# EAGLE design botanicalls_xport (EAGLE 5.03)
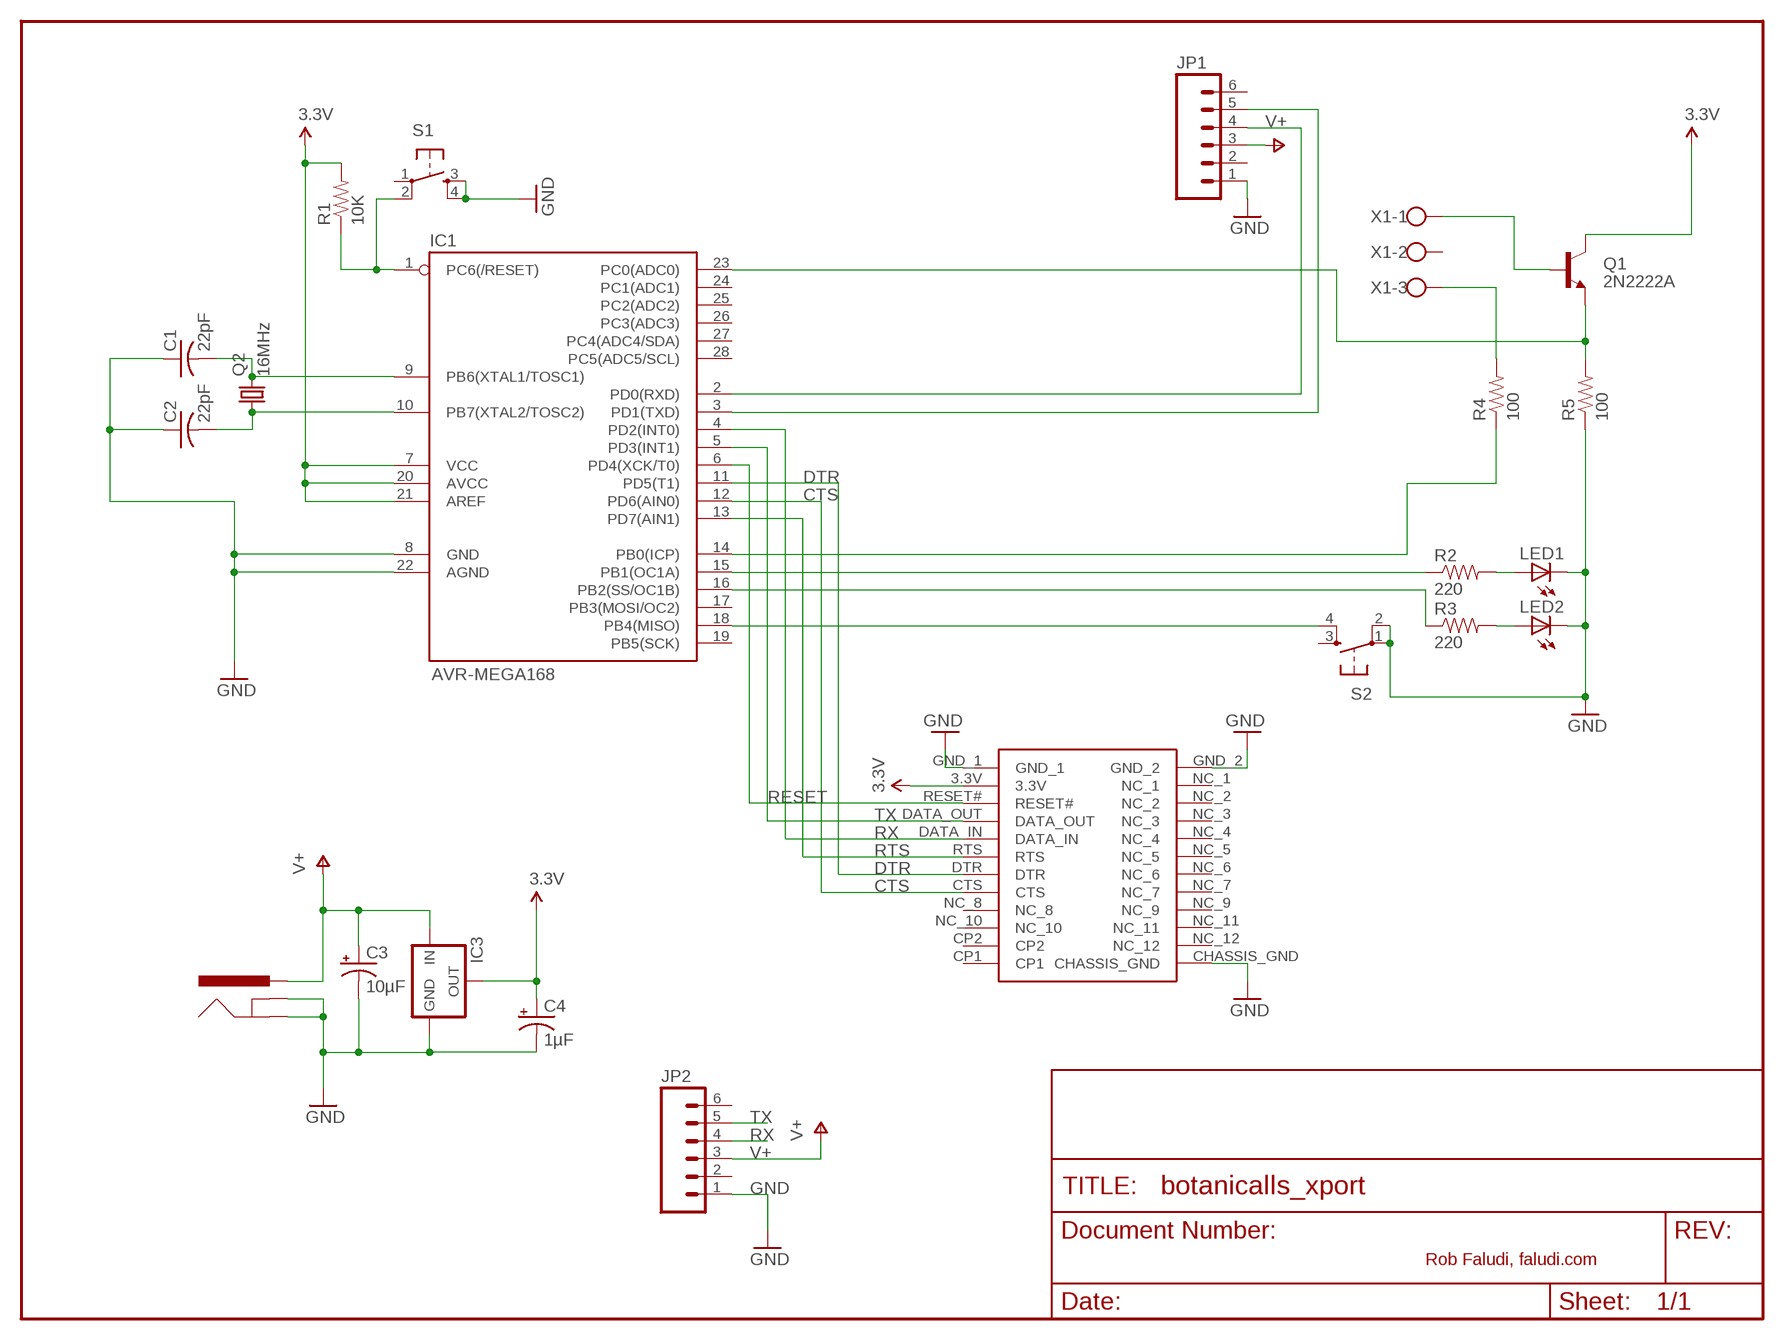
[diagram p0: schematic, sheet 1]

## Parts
C1  22pF  C-US025-025X050  [C025-025X050]
C2  22pF  C-US025-025X050  [C025-025X050]
C3  10µF  CPOL-USE2.5-5  [E2,5-5]
C4  1µF  CPOL-USE2.5-5  [E2,5-5]
IC1  AVR-MEGA168  AVR-MEGA8-P  [DIL28-3]
IC3  LD1117  [LD1117]
J1  POWER_JACKPTH  [POWER_JACK_PTH]
JP1  M06SIP  [1X06]
JP2  M06SIP  [1X06]
LED1  LED3MM  [LED3MM]
LED2  LED3MM  [LED3MM]
Q1  2N2222A  TRANSISTOR_NPNTO92  [TO-92]
Q2  16MHz  CRYTALHC49U-V  [HC49U-V]
R1  10K  RESISTORPTH1  [AXIAL-0.3]
R2  220  RESISTORPTH1  [AXIAL-0.3]
R3  220  RESISTORPTH1  [AXIAL-0.3]
R4  100  RESISTORPTH1  [AXIAL-0.3]
R5  100  RESISTORPTH1  [AXIAL-0.3]
S1  TAC_SWITCHPTH  [TACTILE-PTH]
S2  TAC_SWITCHPTH  [TACTILE-PTH]
U$3  LANTRONIX-XPORT-DIRECT  [XPORT-DIRECT-2MM]
X1  W237-03P  [W237-133]

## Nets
3.3V: C4.+ IC1.7(VCC) IC1.20(AVCC) IC1.21(AREF) IC3.GND Q1.3(C) R1.P$2 U$3.3.3V
CTS: IC1.12(PD6(AIN0)) U$3.CTS
DTR: IC1.11(PD5(T1)) U$3.DTR
GND: C1.1 C2.1 C3.- C4.- IC1.8(GND) IC1.22(AGND) IC3.IN J1.GND J1.GNDBREAK JP1.1 JP2.1 LED1.K(C) LED2.K(C) R5.P$1 S1.3 S1.4 S2.1 S2.2 U$3.CHASSIS_GND U$3.GND_1 U$3.GND_2
N$1: IC1.15(PB1(OC1A)) R2.P$1
N$2: C1.2 IC1.9(PB6(XTAL1/TOSC1)) Q2.2
N$3: IC1.2(PD0(RXD)) JP1.4
N$4: IC1.1(PC6(/RESET)) R1.P$1 S1.2
N$5: C2.2 IC1.10(PB7(XTAL2/TOSC2)) Q2.1
N$6: IC1.3(PD1(TXD)) JP1.5
N$7: IC1.18(PB4(MISO)) S2.4
N$8: IC1.16(PB2(SS/OC1B)) R3.P$1
N$9: LED2.A R3.P$2
N$10: IC1.14(PB0(ICP)) R4.P$1
N$11: LED1.A R2.P$2
N$13: R4.P$2 X1.3
N$14: Q1.2(B) X1.1
N$15: IC1.23(PC0(ADC0)) Q1.1(E) R5.P$2
RESET: IC1.6(PD4(XCK/T0)) U$3.RESET#
RTS: IC1.13(PD7(AIN1)) U$3.RTS
RX: IC1.4(PD2(INT0)) JP2.4 U$3.DATA_IN
TX: IC1.5(PD3(INT1)) JP2.5 U$3.DATA_OUT
V+: C3.+ IC3.OUT J1.PWR JP1.3 JP2.3
Unconnected: IC1.17(PB3(MOSI/OC2)) IC1.19(PB5(SCK)) IC1.24(PC1(ADC1)) IC1.25(PC2(ADC2)) IC1.26(PC3(ADC3)) IC1.27(PC4(ADC4/SDA)) IC1.28(PC5(ADC5/SCL)) JP1.2 JP1.6 JP2.2 JP2.6 S1.1 S2.3 U$3.CP1 U$3.CP2 U$3.NC_1 U$3.NC_2 U$3.NC_3 U$3.NC_4 U$3.NC_5 U$3.NC_6 U$3.NC_7 U$3.NC_8 U$3.NC_9 U$3.NC_10 U$3.NC_11 U$3.NC_12 X1.2

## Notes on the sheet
- Rob Faludi, faludi.com

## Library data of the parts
C1 C2 = rcl:C-US: CAPACITOR, American symbol
C3 C4 = rcl:CPOL-US: POLARIZED CAPACITOR, American symbol
IC1 = SparkFun:AVR-MEGA8-P: MICROCONTROLLER 8 Kbytes FLASH 1 kbytes SRAM 512 bytes EEPROM USART 4-channel 10 bit ADC 2-channel 8 bit ADC
IC3 = LD1117:LD1117: VOLTAGE REGULATOR
J1 = SparkFun:POWER_JACK: Power Jack This is the standard 5.5mm barrel jack for power. The PTH is the most common, proven, reliable, footprint. All others are experimental. The Slot footprint only works if the mill layer is transmitted to the PCB fab house so be warned. Spark Fun Electronics SKU : PRT-00119. Mating wall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
JP1 JP2 = SparkFun:M06: Header 6 Standard 6-pin 0.1" header. Use with straight break away headers (SKU : PRT-00116), right angle break away headers (PRT-00553), swiss pins (PRT-00743), machine pins (PRT-00117), and female headers (PRT-00115). Molex polarized connector foot print use with SKU : PRT-08094 with associated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
LED1 LED2 = SparkFun:LED: LEDs
Q1 = SparkFun:TRANSISTOR_NPN: Transistor NPN BJT configuration in SOT23 package. MMBT2222 is the common NPN we use. Double check BCE configuration again layout.
Q2 = crystal:CRYTAL: CRYSTAL
R1-R5 = SparkFun:RESISTOR: Resistor
S1 S2 = SparkFun:TAC_SWITCH: Momentary Switch Button commonly used for reset or general input. Spark Fun Electronics SKU : COM-00097
U$3 = Lantronix-Xport-Direct:LANTRONIX-XPORT-DIRECT
X1 = con-wago-508:W237-03P: WAGO SREW CLAMP

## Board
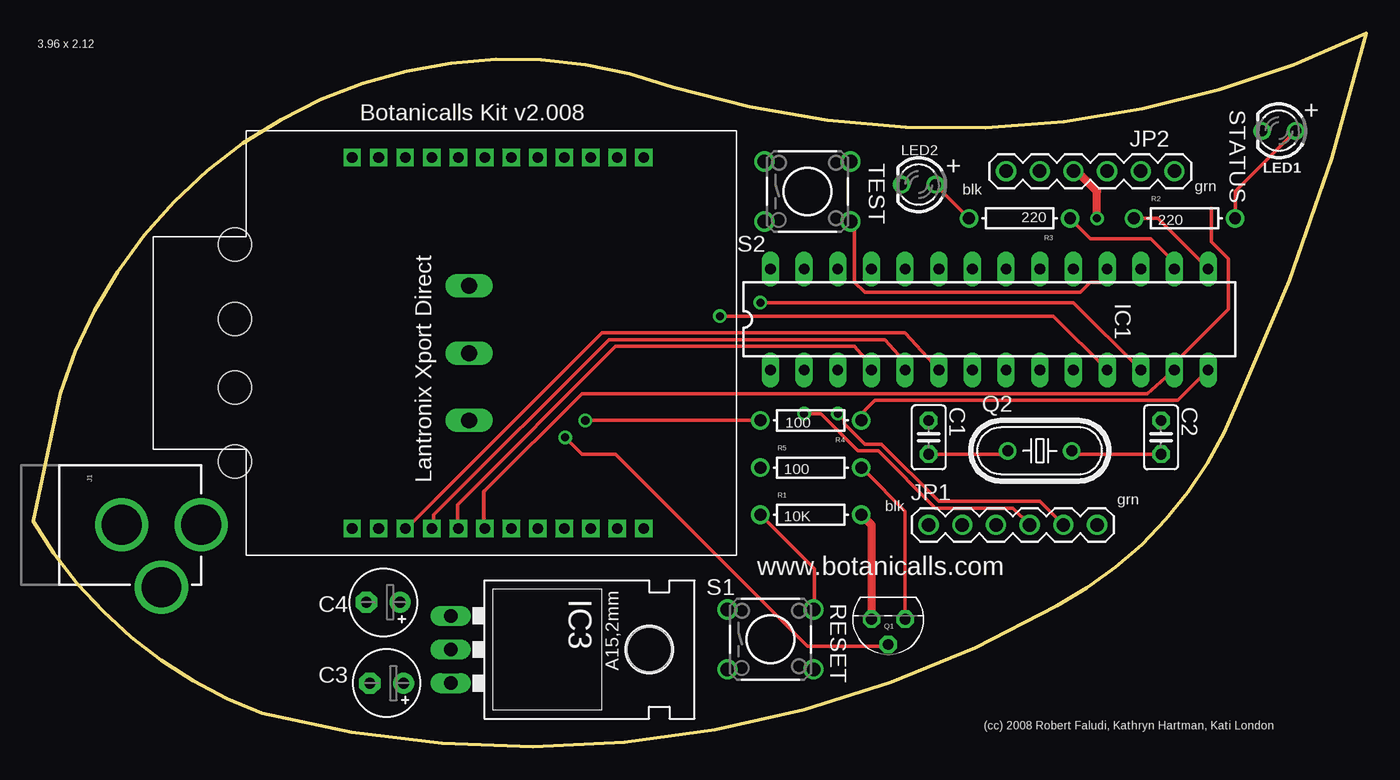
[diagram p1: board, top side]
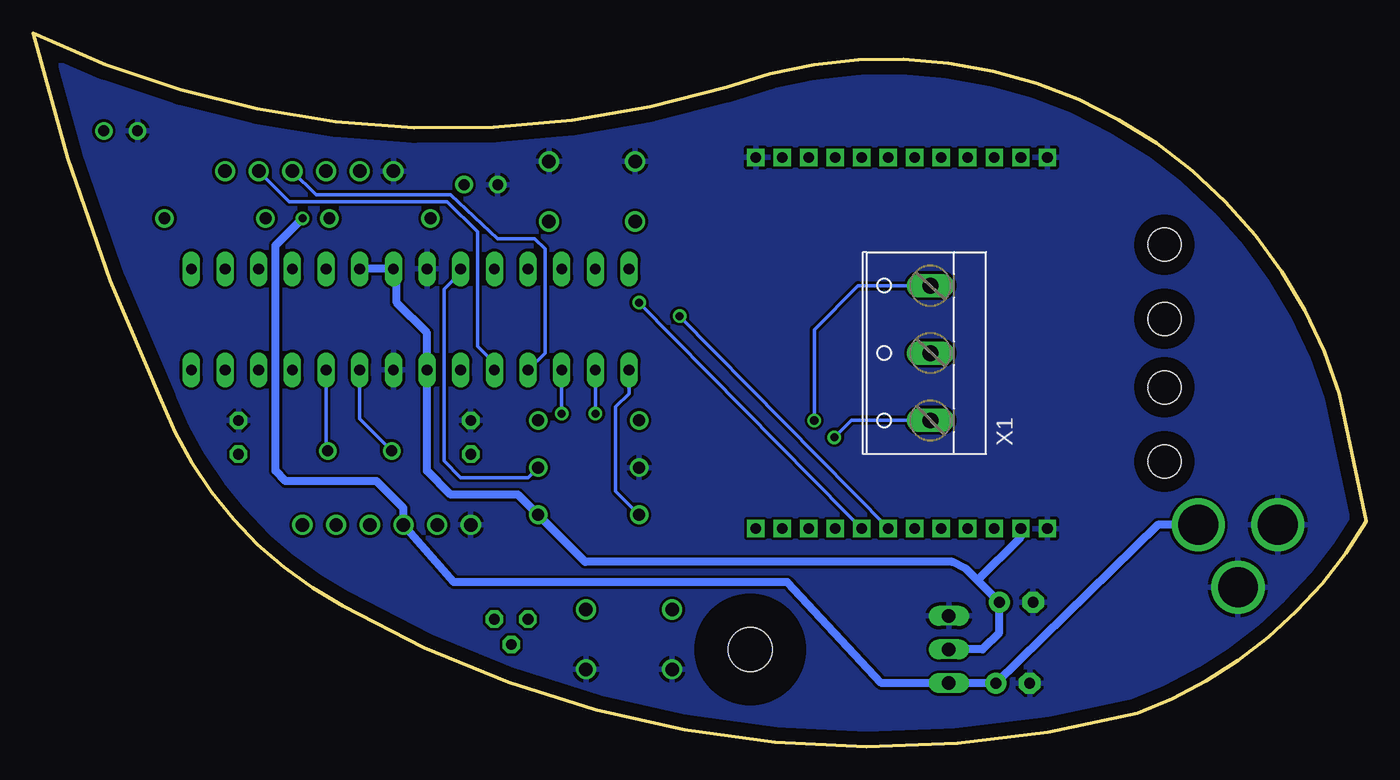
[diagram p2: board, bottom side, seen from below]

Size 100.58 x 53.81 mm. Coordinates in mm from the lower left corner, seen from the top.
Outline: 0,16.98 arc39 17.27,2.5 arc44 77.22,10.63 arc41 90.93,26.13 arc11 100.58,53.81 arc-43 48.26,49.75 arc93 2.03,26.63 0,16.98
Copper layers (1*16): Top 0.035mm / dielectric 1.5mm / Bottom 0.035mm
Design rules "default": minimum track width 10mil, minimum drill 24mil, track to track 8mil, track to pad 8mil, pad to pad 8mil, via to via 8mil, smd to smd 8mil, copper to edge 40mil, drill to drill 8mil, minimum pad ring 10mil, minimum via ring 8mil, stop-mask expansion 4mil, vias tented up to drill 0mil, thermal gap 10mil
Holes 2.5 mm at 15.24,37.86 15.24,32.27 15.24,27.1 15.24,21.51

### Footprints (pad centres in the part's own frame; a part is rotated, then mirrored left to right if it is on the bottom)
C025-025X050 = drill 0.813 octagon: 1 -1.27,0; 2 1.27,0
E2,5-5 = drill 0.813 pad 1.6 round: + -1.27,0 | drill 0.813 pad 1.6 octagon: - 1.27,0
DIL28-3 = drill 0.813 long: 1 -16.51,-3.81; 2 -13.97,-3.81; 3 -11.43,-3.81; 4 -8.89,-3.81; 5 -6.35,-3.81; 6 -3.81,-3.81; 7 -1.27,-3.81; 8 1.27,-3.81; 9 3.81,-3.81; 10 6.35,-3.81; 11 8.89,-3.81; 12 11.43,-3.81; 13 13.97,-3.81; 14 16.51,-3.81; 15 16.51,3.81; 16 13.97,3.81; 17 11.43,3.81; 18 8.89,3.81; 19 6.35,3.81; 20 3.81,3.81; 21 1.27,3.81; 22 -1.27,3.81; 23 -3.81,3.81; 24 -6.35,3.81; 25 -8.89,3.81; 26 -11.43,3.81; 27 -13.97,3.81; 28 -16.51,3.81
LD1117 = drill 1.016 long: GND 0,-3.81; IN -2.54,-3.81; OUT 2.54,-3.81 | hole 3.302: 0,11.176
POWER_JACK_PTH = drill 2.997 round: GND 0,7.7; GNDBREAK 4.7,10.7; PWR 0,13.7
1X06 = drill 1.016 round: 1 0,0; 2 2.54,0; 3 5.08,0; 4 7.62,0; 5 10.16,0; 6 12.7,0
LED3MM = drill 0.813 round: A -1.27,0; K 1.27,0
TO-92 = drill 0.813 octagon: 1 -1.27,0; 2 0,1.905; 3 1.27,0
HC49U-V = drill 0.813 round: 1 -2.413,0; 2 2.413,0
AXIAL-0.3 = drill 0.9 round: P$1 -3.81,0; P$2 3.81,0
TACTILE-PTH = drill 1.016 round: 1 -3.251,2.261; 2 3.251,2.261; 3 -3.251,-2.261; 4 3.251,-2.261
XPORT-DIRECT-2MM = drill 0.8 square: 3.3V -14,10; CHASSIS_GND 14,-10; CP1 -14,-10; CP2 -14,-8; CTS -14,-2; DATA_IN -14,4; DATA_OUT -14,6; DTR -14,0; GND_1 -14,12; GND_2 14,12; NC_1 14,10; NC_2 14,8; NC_3 14,6; NC_4 14,4; NC_5 14,2; NC_6 14,0; NC_7 14,-2; NC_8 -14,-4; NC_9 14,-4; NC_10 -14,-6; NC_11 14,-6; NC_12 14,-8; RESET# -14,8; RTS -14,2
W237-133 = drill 1.194 long: 1 -5.08,-0.635; 2 0,-0.635; 3 5.08,-0.635

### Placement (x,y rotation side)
C1  67.56,23.33 270 top
C2  85.09,23.33 270 top
C3  26.67,4.79 180 top
C4  26.42,10.89 180 top
IC1  72.14,32.22 0 top
IC3  35.31,7.33 270 top
J1  -1.02,16.73 270 top
JP1  67.56,16.73 0 top
JP2  73.41,43.4 0 top
LED1  93.98,46.45 180 top
LED2  66.8,42.38 180 top
Q1  64.52,9.62 180 top
Q2  75.95,22.32 180 top
R1  58.67,17.49 0 top
R2  86.87,39.84 0 top
R3  74.42,39.84 180 top
R4  58.67,24.6 180 top
R5  58.67,21.05 0 top
S1  55.63,8.09 0 top
S2  58.42,41.87 0 top
U$3  36.07,30.44 90 top
X1  33.53,29.68 90 bottom

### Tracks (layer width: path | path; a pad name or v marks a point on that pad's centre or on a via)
3.3V
  Top 0.61: Q1.3 63.25,16.73 R1.P$2
  Bottom 0.61: IC3.GND 28.96,7.33 27.69,8.6 C4.+ 29.34,12.54 | IC1.20 75.95,36.29 75.69,36.03 IC1.21 73.41,35.78 73.15,35.52 73.15,33.49 70.87,31.21 IC1.7 70.87,20.79 69.09,19.01 64.01,19.01 R1.P$2 | 29.34,12.54 30.23,13.43 31.24,13.93 58.93,13.93 R1.P$2 | R1.P$2 62.48,17.24 | U$3.3.3V 26.07,15.81 29.34,12.54
CTS  (via drill 0.61)
  Top 0.254: IC1.12 78.49,33.49 v54.86,33.49
  Bottom 0.254: v54.86,33.49 39.12,17.49 38.1,16.47
  Bottom 0.305: U$3.CTS 38.1,16.41 38.1,16.47
DTR  (via drill 0.61)
  Top 0.254: IC1.11 76.96,32.48 v51.82,32.48
  Bottom 0.254: 36.07,16.47 v51.82,32.48
  Bottom 0.305: U$3.DTR 36.07,16.47
GND
  pour Bottom: -1.02,54.07 -1.02,-0.54 101.35,-0.54 101.35,54.32
N$1
  Top 0.254: R2.P$1 84.84,39.84 IC1.15
N$2
  Top 0.254: Q2.2 73.28,22.06 C1.2
  Bottom 0.254: Q2.2 75.95,24.73 IC1.9
N$3  (via drill 0.61)
  Top 0.254: v58.17,25.11 59.44,25.11 62.23,22.32 63.75,22.32 68.07,18 73.91,18 JP1.4
  Bottom 0.254: v58.17,25.11 IC1.2
N$4
  Top 0.254: 58.93,10.3 58.93,10.12 | S1.2 58.93,10.3 | R1.P$1 58.93,13.43 58.93,10.3
  Bottom 0.254: IC1.1 55.63,26.63 56.64,25.62 56.64,19.27 R1.P$1
N$5
  Top 0.254: Q2.1 78.61,22.06 C2.2
  Bottom 0.254: Q2.1 78.36,22.44 78.49,22.57 IC1.10
N$6  (via drill 0.61)
  Top 0.254: v60.71,25.11 61.21,24.6 61.21,24.35 62.74,22.82 64.01,22.82 68.33,18.51 75.95,18.51 JP1.5
  Bottom 0.254: v60.71,25.11 IC1.3
N$7
  Top 0.254: IC1.18 80.52,35.02 79.76,35.02 78.99,34.25 62.74,34.25 61.98,35.02 61.98,39.08 S2.4
N$8
  Top 0.254: IC1.16 86.11,36.54 84.33,38.32 79.76,38.32 R3.P$1
N$9
  Top 0.254: LED2.A 68.33,42.38 68.33,42.13 R3.P$2
N$10
  Top 0.254: IC1.14 86.36,26.13 63.5,26.13 62.48,25.11 R4.P$1
N$11
  Top 0.254: R2.P$2 90.68,41.87 LED1.A
N$13  (via drill 0.61)
  Top 0.254: v41.66,24.6 R4.P$2
  Bottom 0.254: 32.77,34.76 X1.3 38.35,34.76 41.66,31.46 v41.66,24.6
N$14  (via drill 0.61)
  Top 0.254: v40.13,23.33 41.4,22.06 43.94,22.06 58.42,7.58 64.26,7.58 64.52,7.84 Q1.2
  Bottom 0.254: X1.1 32.89,24.47 33.02,24.35 33.27,24.6 38.86,24.6 v40.13,23.33
N$15
  Top 0.254: Q1.1 65.79,17.74 62.74,20.79 62.48,20.79 R5.P$2
  Bottom 0.254: R5.P$2 63.25,20.28 68.33,20.28 69.6,21.55 69.6,34.51 68.33,35.78 IC1.23
RESET
  Top 0.254: IC1.6 65.79,31.21 42.93,31.21 28.45,16.73
  Top 0.305: U$3.RESET# 28.19,16.57 28.19,16.73 28.45,16.73
RTS
  Top 0.254: 34.04,19.27 41.4,26.63 84.07,26.63 IC1.13 86.36,29.17 90.17,32.98 90.17,36.79 88.9,38.06 88.9,40.6
  Top 0.305: 34.04,19.27 34.04,16.47 U$3.RTS
RX
  Top 0.254: IC1.4 63.5,28.41 61.98,30.19 43.94,30.19 32,18.25 32.04,16.47 U$3.DATA_IN
  Bottom 0.254: JP2.4 79.25,41.62 69.09,41.62 65.53,38.32 62.74,38.32 61.98,37.56 61.98,29.68 IC1.4
TX
  Top 0.254: IC1.5 66.29,28.41 64.26,30.7 43.43,30.7 30.23,17.49 30.23,16.47 30.1,16.47 U$3.DATA_OUT
  Bottom 0.254: JP2.5 81.28,41.11 69.34,41.11 67.06,38.83 67.06,30.19 65.79,28.92 IC1.5 65.79,28.16
V+  (via drill 0.61)
  Top 0.61: v80.26,39.84 80.26,41.87 78.74,43.4 JP2.3
  Bottom 0.61: C3.+ 28.19,4.54 | J1.PWR 15.75,16.73 C3.+ | C3.+ IC3.OUT 36.58,4.79 43.69,12.41 68.83,12.41 JP1.3 72.64,18 74.68,20.03 81.53,20.03 82.3,20.79 82.3,37.81 v80.26,39.84

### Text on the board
tPlace: 3.96 x 2.12 | Botanicalls Kit v2.008 | STATUS | + | TEST | + | blk | grn | grn | blk | www.botanicalls.com | RESET | (cc) 2008 Robert Faludi, Kathryn Hartman, Kati London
